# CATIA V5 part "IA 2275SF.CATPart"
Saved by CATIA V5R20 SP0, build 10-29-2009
Part number: IA 2275SF
Revision: ANY
Definition: UNKNOWN
Nomenclature: IA 2275SF
Source: Unknown
Bounding box of the stored display mesh (mm): x -1.102 to 1.102, y -0.001 to 7.75, z -1.102 to 1.102
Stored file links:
  C:\Users\Utente\Desktop\IO LAVORO\3D X SITO CF\CUMSA\3D files IA\IA 2275SF\IA 2275SF.CATPart
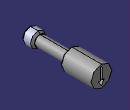
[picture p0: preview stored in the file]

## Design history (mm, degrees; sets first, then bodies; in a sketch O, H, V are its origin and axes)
Body1 "Cortar-Extruir2" (main body)
  Solid1: solid without history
